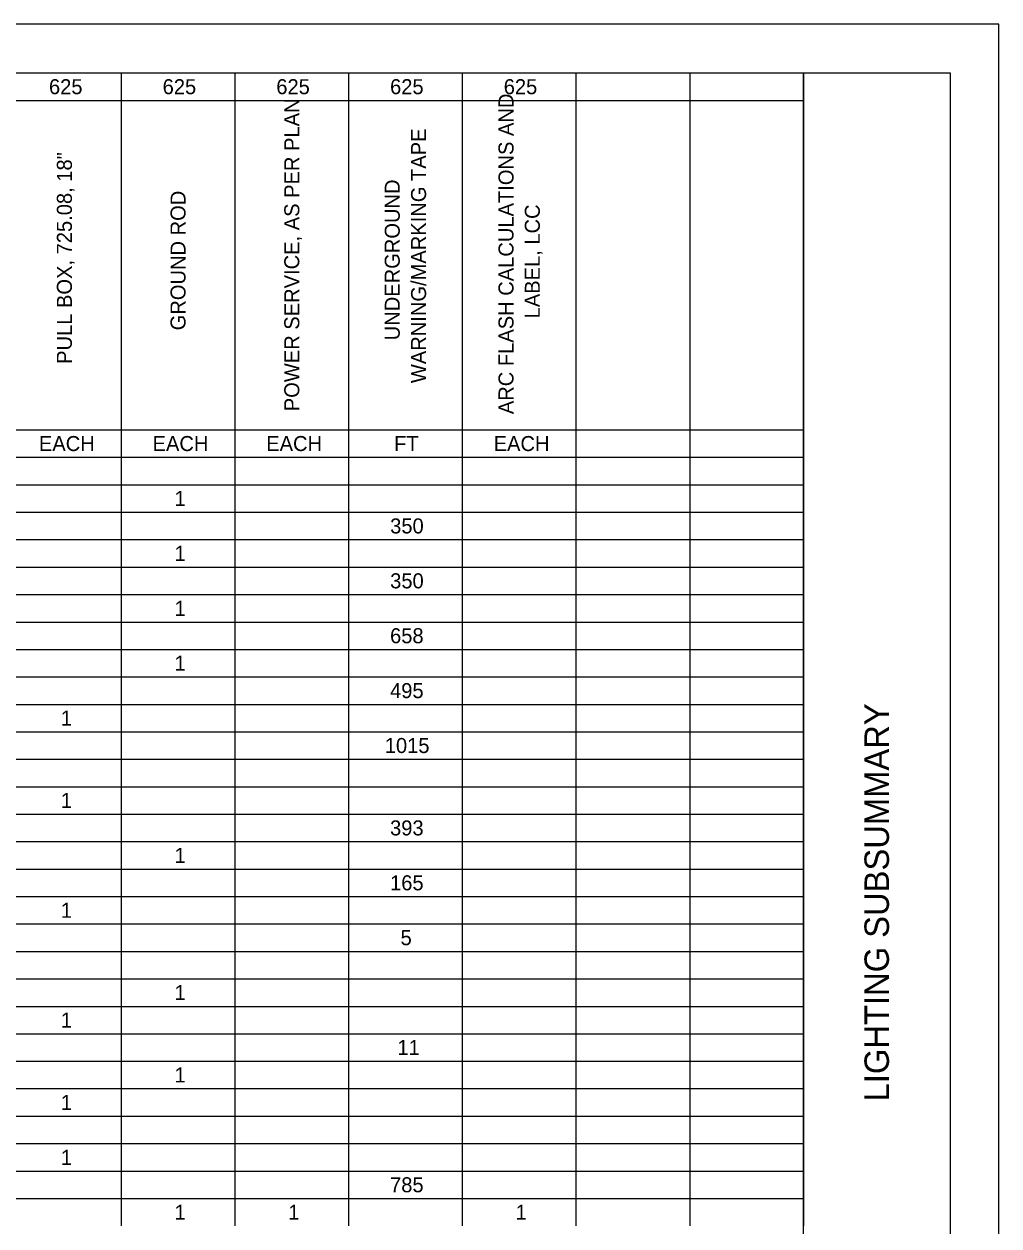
# Model space of a CAD drawing. Extents: x 0 to 34, y 0 to 22.
# Drawn here: x 24.03 to 34, y 9.72 to 22 of the extents above; entities that cross this region are included whole.
import ezdxf

# ---------------------------------------------------------------- set-up
doc = ezdxf.new("R2010")
doc.units = 0
for name, color, linetype in [('SH_Border', 7, 'Continuous'), ('SH_Cut_Line', 7, 'Continuous'), ('SH_Data', 7, 'Continuous'), ('SH_Text', 7, 'Continuous')]:
    doc.layers.add(name, color=color, linetype=linetype)

msp = doc.modelspace()

# ---------------------------------------------------------------- linework, layer by layer
at = {"layer": 'SH_Border'}
msp.add_line((32, 0.5), (32, 21.5), dxfattribs=at)
msp.add_lwpolyline([(1.5, 21.5), (33.5, 21.5), (33.5, 0.5), (1.5, 0.5)], close=True, dxfattribs=at)
at = {"layer": 'SH_Cut_Line'}
msp.add_lwpolyline([(0, 0), (34, 0), (34, 22), (0, 22)], close=True, dxfattribs=at)
at = {"layer": 'SH_Text'}
for p, q in [((16.89, 21.5), (25.026, 21.5)), ((25.026, 21.5), (26.189, 21.5)), ((25.026, 21.5), (25.026, 21.219)), ((26.189, 21.5), (28.513, 21.5)), ((26.189, 21.5), (26.189, 21.219)), ((27.351, 21.5), (27.351, 21.219)), ((28.513, 21.5), (32, 21.5)), ((28.513, 21.5), (28.513, 21.219)), ((29.675, 21.5), (29.675, 21.219)), ((30.838, 21.5), (30.838, 21.219)), ((32, 21.5), (32, 21.219)), ((16.89, 21.219), (25.026, 21.219)), ((25.026, 21.219), (26.189, 21.219)), ((25.026, 21.219), (25.026, 20.939)), ((26.189, 21.219), (28.513, 21.219)), ((26.189, 21.219), (26.189, 20.939)), ((27.351, 21.219), (27.351, 20.939)), ((28.513, 21.219), (32, 21.219)), ((28.513, 21.219), (28.513, 20.939)), ((29.675, 21.219), (29.675, 20.939)), ((30.838, 21.219), (30.838, 20.939)), ((32, 21.219), (32, 20.939)), ((25.026, 20.939), (25.026, 20.658)), ((26.189, 20.939), (26.189, 20.658)), ((27.351, 20.939), (27.351, 20.658)), ((28.513, 20.939), (28.513, 20.658)), ((29.675, 20.939), (29.675, 20.658)), ((30.838, 20.939), (30.838, 20.658)), ((32, 20.939), (32, 20.658)), ((25.026, 20.658), (25.026, 20.378)), ((26.189, 20.658), (26.189, 20.378)), ((27.351, 20.658), (27.351, 20.378)), ((28.513, 20.658), (28.513, 20.378)), ((29.675, 20.658), (29.675, 20.378)), ((30.838, 20.658), (30.838, 20.378)), ((32, 20.658), (32, 20.378)), ((25.026, 20.378), (25.026, 20.097)), ((26.189, 20.378), (26.189, 20.097)), ((27.351, 20.378), (27.351, 20.097)), ((28.513, 20.378), (28.513, 20.097)), ((29.675, 20.378), (29.675, 20.097)), ((30.838, 20.378), (30.838, 20.097)), ((32, 20.378), (32, 20.097)), ((25.026, 20.097), (25.026, 19.817)), ((26.189, 20.097), (26.189, 19.817)), ((27.351, 20.097), (27.351, 19.817)), ((28.513, 20.097), (28.513, 19.817)), ((29.675, 20.097), (29.675, 19.817)), ((30.838, 20.097), (30.838, 19.817)), ((32, 20.097), (32, 19.817)), ((25.026, 19.817), (25.026, 19.536)), ((26.189, 19.817), (26.189, 19.536)), ((27.351, 19.817), (27.351, 19.536)), ((28.513, 19.817), (28.513, 19.536)), ((29.675, 19.817), (29.675, 19.536)), ((30.838, 19.817), (30.838, 19.536)), ((32, 19.817), (32, 19.536)), ((25.026, 19.536), (25.026, 18.975)), ((26.189, 19.536), (26.189, 18.975)), ((27.351, 19.536), (27.351, 18.975)), ((28.513, 19.536), (28.513, 18.975)), ((29.675, 19.536), (29.675, 18.975)), ((30.838, 19.536), (30.838, 18.975)), ((32, 19.536), (32, 18.975)), ((25.026, 18.975), (25.026, 18.133)), ((26.189, 18.975), (26.189, 18.133)), ((27.351, 18.975), (27.351, 18.133)), ((28.513, 18.975), (28.513, 18.133)), ((29.675, 18.975), (29.675, 18.133)), ((30.838, 18.975), (30.838, 18.133)), ((32, 18.975), (32, 18.133)), ((25.026, 18.133), (25.026, 17.853)), ((26.189, 18.133), (26.189, 17.853)), ((27.351, 18.133), (27.351, 17.853)), ((28.513, 18.133), (28.513, 17.853)), ((29.675, 18.133), (29.675, 17.853)), ((30.838, 18.133), (30.838, 17.853)), ((32, 18.133), (32, 17.853)), ((16.89, 17.853), (25.026, 17.853)), ((25.026, 17.853), (26.189, 17.853)), ((25.026, 17.853), (25.026, 17.292)), ((26.189, 17.853), (28.513, 17.853)), ((26.189, 17.853), (26.189, 17.292)), ((27.351, 17.853), (27.351, 17.292)), ((28.513, 17.853), (32, 17.853)), ((28.513, 17.853), (28.513, 17.292)), ((29.675, 17.853), (29.675, 17.292)), ((30.838, 17.853), (30.838, 17.292)), ((32, 17.853), (32, 17.292)), ((16.89, 17.572), (25.026, 17.572)), ((25.026, 17.572), (26.189, 17.572)), ((26.189, 17.572), (28.513, 17.572)), ((28.513, 17.572), (32, 17.572)), ((16.89, 17.292), (25.026, 17.292)), ((25.026, 17.292), (26.189, 17.292)), ((25.026, 17.292), (25.026, 17.011)), ((26.189, 17.292), (28.513, 17.292)), ((26.189, 17.292), (26.189, 17.011)), ((27.351, 17.292), (27.351, 17.011)), ((28.513, 17.292), (32, 17.292)), ((28.513, 17.292), (28.513, 17.011)), ((29.675, 17.292), (29.675, 17.011)), ((30.838, 17.292), (30.838, 17.011)), ((32, 17.292), (32, 17.011)), ((16.89, 17.011), (25.026, 17.011)), ((25.026, 17.011), (26.189, 17.011)), ((25.026, 17.011), (25.026, 15.889)), ((26.189, 17.011), (28.513, 17.011)), ((26.189, 17.011), (26.189, 15.889)), ((27.351, 17.011), (27.351, 15.889)), ((28.513, 17.011), (32, 17.011)), ((28.513, 17.011), (28.513, 15.889)), ((29.675, 17.011), (29.675, 15.889)), ((30.838, 17.011), (30.838, 15.889)), ((32, 17.011), (32, 15.889)), ((16.89, 16.731), (25.026, 16.731)), ((25.026, 16.731), (26.189, 16.731)), ((26.189, 16.731), (28.513, 16.731)), ((28.513, 16.731), (32, 16.731)), ((16.89, 16.45), (25.026, 16.45)), ((25.026, 16.45), (26.189, 16.45)), ((26.189, 16.45), (28.513, 16.45)), ((28.513, 16.45), (32, 16.45)), ((16.89, 16.17), (25.026, 16.17)), ((25.026, 16.17), (26.189, 16.17)), ((26.189, 16.17), (28.513, 16.17)), ((28.513, 16.17), (32, 16.17)), ((16.89, 15.889), (25.026, 15.889)), ((25.026, 15.889), (26.189, 15.889)), ((25.026, 15.889), (25.026, 15.608)), ((26.189, 15.889), (28.513, 15.889)), ((26.189, 15.889), (26.189, 15.608)), ((27.351, 15.889), (27.351, 15.608)), ((28.513, 15.889), (32, 15.889)), ((28.513, 15.889), (28.513, 15.608)), ((29.675, 15.889), (29.675, 15.608)), ((30.838, 15.889), (30.838, 15.608)), ((32, 15.889), (32, 15.608)), ((16.89, 15.608), (25.026, 15.608)), ((25.026, 15.608), (26.189, 15.608)), ((25.026, 15.608), (25.026, 15.047)), ((26.189, 15.608), (28.513, 15.608)), ((26.189, 15.608), (26.189, 15.047)), ((27.351, 15.608), (27.351, 15.047)), ((28.513, 15.608), (32, 15.608)), ((28.513, 15.608), (28.513, 15.047)), ((29.675, 15.608), (29.675, 15.047)), ((30.838, 15.608), (30.838, 15.047)), ((32, 15.608), (32, 15.047)), ((16.89, 15.328), (25.026, 15.328)), ((25.026, 15.328), (26.189, 15.328)), ((26.189, 15.328), (28.513, 15.328)), ((28.513, 15.328), (32, 15.328)), ((16.89, 15.047), (25.026, 15.047)), ((25.026, 15.047), (26.189, 15.047)), ((25.026, 15.047), (25.026, 14.486)), ((26.189, 15.047), (28.513, 15.047)), ((26.189, 15.047), (26.189, 14.486)), ((27.351, 15.047), (27.351, 14.486)), ((28.513, 15.047), (32, 15.047)), ((28.513, 15.047), (28.513, 14.486)), ((29.675, 15.047), (29.675, 14.486)), ((30.838, 15.047), (30.838, 14.486)), ((32, 15.047), (32, 14.486)), ((16.89, 14.767), (25.026, 14.767)), ((25.026, 14.767), (26.189, 14.767)), ((26.189, 14.767), (28.513, 14.767)), ((28.513, 14.767), (32, 14.767)), ((16.89, 14.486), (25.026, 14.486)), ((25.026, 14.486), (26.189, 14.486)), ((25.026, 14.486), (25.026, 14.206)), ((26.189, 14.486), (28.513, 14.486)), ((26.189, 14.486), (26.189, 14.206)), ((27.351, 14.486), (27.351, 14.206)), ((28.513, 14.486), (32, 14.486)), ((28.513, 14.486), (28.513, 14.206)), ((29.675, 14.486), (29.675, 14.206)), ((30.838, 14.486), (30.838, 14.206)), ((32, 14.486), (32, 14.206)), ((16.89, 14.206), (25.026, 14.206)), ((25.026, 14.206), (26.189, 14.206)), ((25.026, 14.206), (25.026, 13.645)), ((26.189, 14.206), (28.513, 14.206)), ((26.189, 14.206), (26.189, 13.645)), ((27.351, 14.206), (27.351, 13.645)), ((28.513, 14.206), (32, 14.206)), ((28.513, 14.206), (28.513, 13.645)), ((29.675, 14.206), (29.675, 13.645)), ((30.838, 14.206), (30.838, 13.645)), ((32, 14.206), (32, 13.645)), ((16.89, 13.925), (25.026, 13.925)), ((25.026, 13.925), (26.189, 13.925)), ((26.189, 13.925), (28.513, 13.925)), ((28.513, 13.925), (32, 13.925)), ((16.89, 13.645), (25.026, 13.645)), ((25.026, 13.645), (26.189, 13.645)), ((25.026, 13.645), (25.026, 13.364)), ((26.189, 13.645), (28.513, 13.645)), ((26.189, 13.645), (26.189, 13.364)), ((27.351, 13.645), (27.351, 13.364)), ((28.513, 13.645), (32, 13.645)), ((28.513, 13.645), (28.513, 13.364)), ((29.675, 13.645), (29.675, 13.364)), ((30.838, 13.645), (30.838, 13.364)), ((32, 13.645), (32, 13.364)), ((16.89, 13.364), (25.026, 13.364)), ((25.026, 13.364), (26.189, 13.364)), ((25.026, 13.364), (25.026, 12.522)), ((26.189, 13.364), (28.513, 13.364)), ((26.189, 13.364), (26.189, 12.522)), ((27.351, 13.364), (27.351, 12.522)), ((28.513, 13.364), (32, 13.364)), ((28.513, 13.364), (28.513, 12.522)), ((29.675, 13.364), (29.675, 12.522)), ((30.838, 13.364), (30.838, 12.522)), ((32, 13.364), (32, 12.522)), ((16.89, 13.083), (25.026, 13.083)), ((25.026, 13.083), (26.189, 13.083)), ((26.189, 13.083), (28.513, 13.083)), ((28.513, 13.083), (32, 13.083)), ((16.89, 12.803), (25.026, 12.803)), ((25.026, 12.803), (26.189, 12.803)), ((26.189, 12.803), (28.513, 12.803)), ((28.513, 12.803), (32, 12.803)), ((16.89, 12.522), (25.026, 12.522)), ((25.026, 12.522), (26.189, 12.522)), ((25.026, 12.522), (25.026, 11.961)), ((26.189, 12.522), (28.513, 12.522)), ((26.189, 12.522), (26.189, 11.961)), ((27.351, 12.522), (27.351, 11.961)), ((28.513, 12.522), (32, 12.522)), ((28.513, 12.522), (28.513, 11.961)), ((29.675, 12.522), (29.675, 11.961)), ((30.838, 12.522), (30.838, 11.961)), ((32, 12.522), (32, 11.961)), ((16.89, 12.242), (25.026, 12.242)), ((25.026, 12.242), (26.189, 12.242)), ((26.189, 12.242), (28.513, 12.242)), ((28.513, 12.242), (32, 12.242)), ((16.89, 11.961), (25.026, 11.961)), ((25.026, 11.961), (26.189, 11.961)), ((25.026, 11.961), (25.026, 11.12)), ((26.189, 11.961), (28.513, 11.961)), ((26.189, 11.961), (26.189, 11.12)), ((27.351, 11.961), (27.351, 11.12)), ((28.513, 11.961), (32, 11.961)), ((28.513, 11.961), (28.513, 11.12)), ((29.675, 11.961), (29.675, 11.12)), ((30.838, 11.961), (30.838, 11.12)), ((32, 11.961), (32, 11.12)), ((16.89, 11.681), (25.026, 11.681)), ((25.026, 11.681), (26.189, 11.681)), ((26.189, 11.681), (28.513, 11.681)), ((28.513, 11.681), (32, 11.681)), ((16.89, 11.4), (25.026, 11.4)), ((25.026, 11.4), (26.189, 11.4)), ((26.189, 11.4), (28.513, 11.4)), ((28.513, 11.4), (32, 11.4)), ((16.89, 11.12), (25.026, 11.12)), ((25.026, 11.12), (26.189, 11.12)), ((25.026, 11.12), (25.026, 10.558)), ((26.189, 11.12), (28.513, 11.12)), ((26.189, 11.12), (26.189, 10.558)), ((27.351, 11.12), (27.351, 10.558)), ((28.513, 11.12), (32, 11.12)), ((28.513, 11.12), (28.513, 10.558)), ((29.675, 11.12), (29.675, 10.558)), ((30.838, 11.12), (30.838, 10.558)), ((32, 11.12), (32, 10.558)), ((16.89, 10.839), (25.026, 10.839)), ((25.026, 10.839), (26.189, 10.839)), ((26.189, 10.839), (28.513, 10.839)), ((28.513, 10.839), (32, 10.839)), ((16.89, 10.558), (25.026, 10.558)), ((25.026, 10.558), (26.189, 10.558)), ((25.026, 10.558), (25.026, 9.717)), ((26.189, 10.558), (28.513, 10.558)), ((26.189, 10.558), (26.189, 9.717)), ((27.351, 10.558), (27.351, 9.717)), ((28.513, 10.558), (32, 10.558)), ((28.513, 10.558), (28.513, 9.717)), ((29.675, 10.558), (29.675, 9.717)), ((30.838, 10.558), (30.838, 9.717)), ((32, 10.558), (32, 9.717)), ((16.89, 10.278), (25.026, 10.278)), ((25.026, 10.278), (26.189, 10.278)), ((26.189, 10.278), (28.513, 10.278)), ((28.513, 10.278), (32, 10.278)), ((16.89, 9.997), (25.026, 9.997)), ((25.026, 9.997), (26.189, 9.997)), ((26.189, 9.997), (28.513, 9.997)), ((28.513, 9.997), (32, 9.997))]:
    msp.add_line(p, q, dxfattribs=at)

# ---------------------------------------------------------------- texts
at = {"layer": 'SH_Data'}
msp.add_text('LIGHTING SUBSUMMARY', height=0.25, rotation=90, dxfattribs=at).set_placement((32.875, 10.99))
at = {"layer": 'SH_Text'}
for s, height, p in [('625', 0.1536, (24.288, 21.283)), ('625', 0.1536, (25.45, 21.283)), ('625', 0.1536, (26.612, 21.283)), ('625', 0.1536, (27.775, 21.283)), ('625', 0.1536, (28.937, 21.283)), ('EACH', 0.1536, (24.185, 17.636)), ('EACH', 0.1536, (25.347, 17.636)), ('EACH', 0.1536, (26.509, 17.636)), ('FT', 0.1536, (27.816, 17.636)), ('EACH', 0.1536, (28.834, 17.636)), ('1', 0.154, (25.571, 17.075)), ('350', 0.1536, (27.776, 16.794)), ('1', 0.154, (25.571, 16.514)), ('350', 0.1536, (27.776, 16.233)), ('1', 0.154, (25.571, 15.952)), ('658', 0.1536, (27.775, 15.672)), ('1', 0.154, (25.571, 15.391)), ('495', 0.1536, (27.775, 15.111)), ('1', 0.154, (24.409, 14.83)), ('1015', 0.1536, (27.721, 14.55)), ('1', 0.154, (24.409, 13.989)), ('393', 0.1536, (27.775, 13.708)), ('1', 0.154, (25.571, 13.427)), ('165', 0.1536, (27.775, 13.147)), ('1', 0.154, (24.409, 12.866)), ('5', 0.154, (27.882, 12.586)), ('1', 0.154, (25.571, 12.025)), ('1', 0.154, (24.409, 11.744)), ('11', 0.1536, (27.85, 11.464)), ('1', 0.154, (25.571, 11.183)), ('1', 0.154, (24.409, 10.902)), ('1', 0.154, (24.409, 10.341)), ('785', 0.1536, (27.775, 10.061)), ('1', 0.154, (25.571, 9.78)), ('1', 0.154, (26.734, 9.78)), ('1', 0.154, (29.058, 9.78))]:
    msp.add_text(s, height=height, dxfattribs=at).set_placement(p)
for s, height, p in [('ARC FLASH CALCULATIONS AND ', 0.15364, (29.037, 18.013)), ('POWER SERVICE, AS PER PLAN', 0.15364, (26.847, 18.043)), ('WARNING/MARKING TAPE', 0.15364, (28.143, 18.33)), ('PULL BOX, 725.08, 18"', 0.15364, (24.522, 18.527)), ('UNDERGROUND ', 0.15364, (27.874, 18.768)), ('GROUND ROD', 0.1536, (25.684, 18.87)), ('LABEL, LCC', 0.1536, (29.306, 18.992))]:
    msp.add_text(s, height=height, rotation=90, dxfattribs=at).set_placement(p)

doc.saveas('drawing.dxf')
